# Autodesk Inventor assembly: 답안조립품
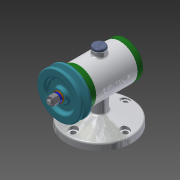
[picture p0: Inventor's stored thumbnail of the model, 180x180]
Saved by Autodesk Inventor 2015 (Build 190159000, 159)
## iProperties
Created: 2018-12
Part Number: 답안조립품
Document SubType Name: Assembly
Designer: CAD02
Author: CAD02
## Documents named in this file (15)
- C:\Users\CAD02\Desktop\481207V1060\답안조립품.iam
- C:\Users\CAD02\Desktop\481207V1060\V벨트풀리.ipt
- C:\Users\CAD02\Desktop\481207V1060\고무캡.ipt
- C:\Users\CAD02\Desktop\481207V1060\너트 M8.ipt
- 너트 M8.ipt
- C:\Users\CAD02\Desktop\481207V1060\뒤커버.ipt
- C:\Users\CAD02\Desktop\481207V1060\베어링 15 x 32 x 9.ipt
- C:\Users\CAD02\Desktop\481207V1060\본체.ipt
- C:\Users\CAD02\Desktop\481207V1060\볼트 M4 x 12.ipt
- C:\Users\CAD02\Desktop\481207V1060\스프링와셔 8.ipt
- C:\Users\CAD02\Desktop\481207V1060\앞커버.ipt
- C:\Users\CAD02\Desktop\481207V1060\오일 실 15 25 7.ipt
- C:\Users\CAD02\Desktop\481207V1060\와셔 8x17.ipt
- C:\Users\CAD02\Desktop\481207V1060\축.ipt
- C:\Users\CAD02\Desktop\481207V1060\키 3 x 3 x 12.ipt
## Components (2 placed, 2 different names)
1. V벨트풀리:1 — 각도:2
2. 고무캡:1
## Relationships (1: Angle 1)
- 각도:2 [Angle]: V벨트풀리:1
